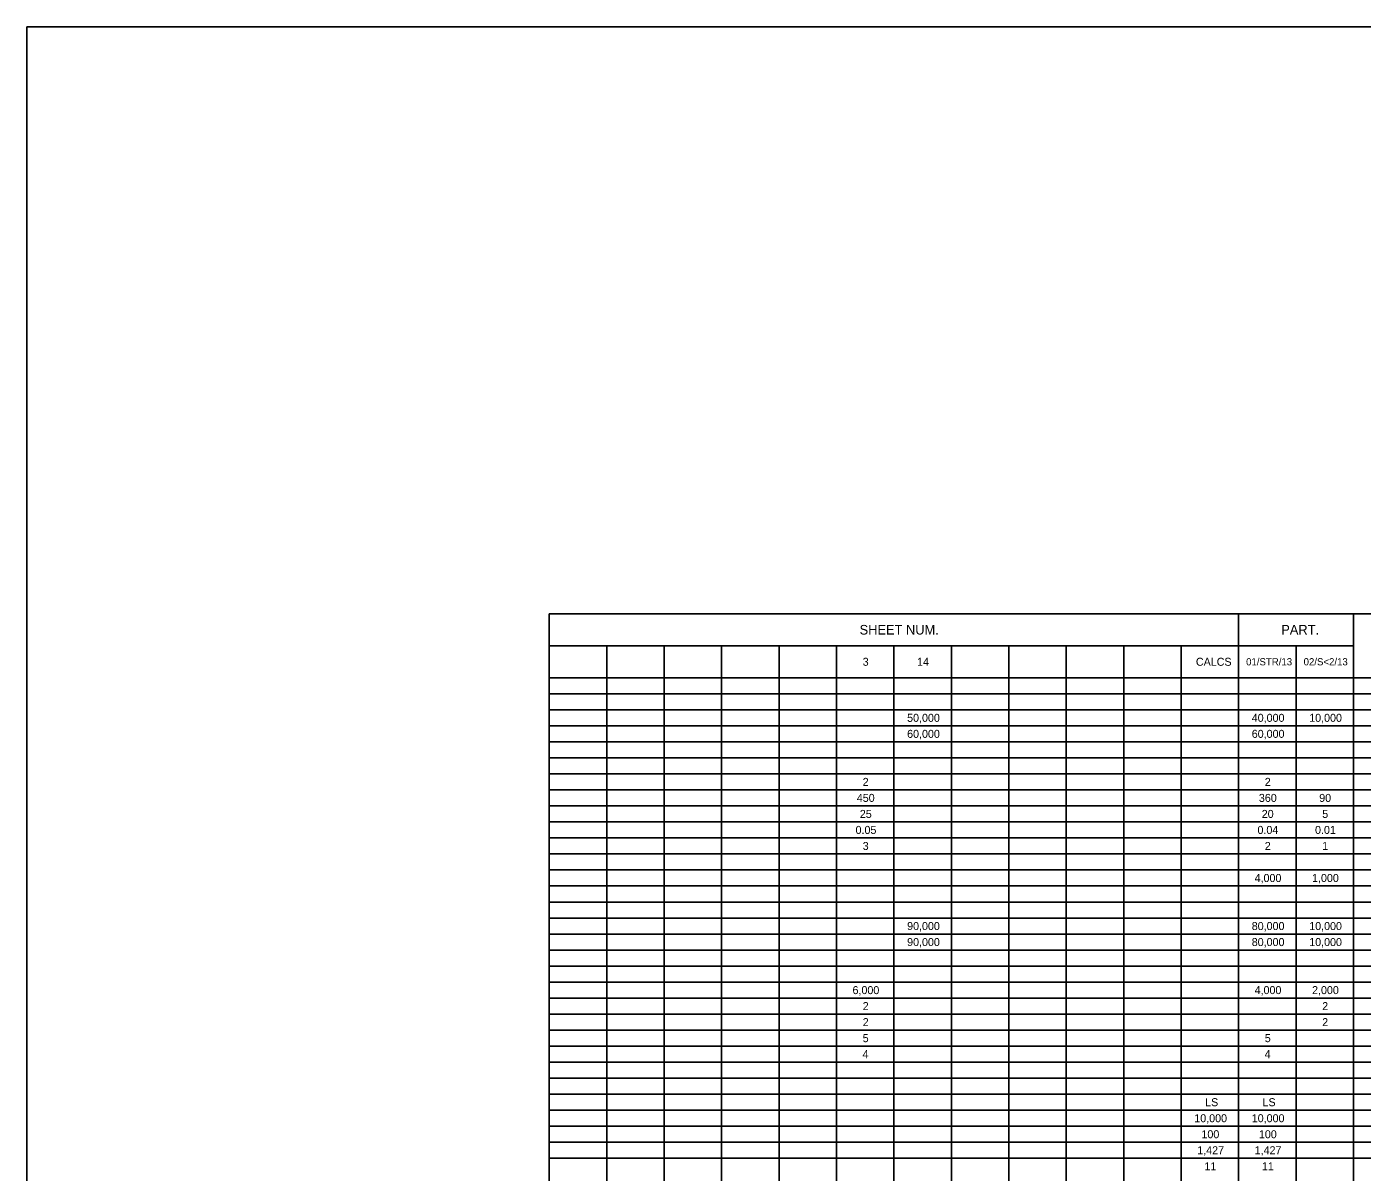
# Model space of a CAD drawing. Extents: x -58.2 to 35.9, y -5.7 to 34.4.
# Drawn here: x -58.21 to -34.85, y 14.42 to 34.45 of the extents above; entities that cross this region are included whole.
import ezdxf

# ---------------------------------------------------------------- set-up
doc = ezdxf.new("R2010")
doc.units = 0
for name, color, linetype in [('SC_Scratch1', 7, 'Continuous'), ('SH_Data', 7, 'Continuous'), ('SH_Text', 7, 'Continuous')]:
    doc.layers.add(name, color=color, linetype=linetype)

msp = doc.modelspace()

# ---------------------------------------------------------------- linework, layer by layer
at = {"layer": 'SC_Scratch1'}
msp.add_lwpolyline([(-58.206, 34.449), (-10.544, 34.449), (-10.544, -5.726), (-58.206, -5.726)], close=True, dxfattribs=at)
at = {"layer": 'SH_Data'}
for p, q in [((-49.066, 24.187), (-18.563, 24.187)), ((-49.066, 24.187), (-49.066, 3.187)), ((-37.01, 24.187), (-37.01, 3.187)), ((-35, 24.187), (-35, 3.187)), ((-49.066, 23.627), (-35, 23.627)), ((-48.061, 23.627), (-48.061, 3.187)), ((-47.057, 23.627), (-47.057, 3.187)), ((-46.052, 23.627), (-46.052, 3.187)), ((-45.047, 23.627), (-45.047, 3.187)), ((-44.043, 23.627), (-44.043, 3.187)), ((-43.038, 23.627), (-43.038, 3.187)), ((-42.033, 23.627), (-42.033, 3.187)), ((-41.028, 23.627), (-41.028, 3.187)), ((-40.024, 23.627), (-40.024, 3.187)), ((-39.019, 23.627), (-39.019, 3.187)), ((-38.014, 23.627), (-38.014, 3.187)), ((-36.005, 23.627), (-36.005, 3.187)), ((-49.066, 23.067), (-18.563, 23.067)), ((-49.066, 22.787), (-18.563, 22.787)), ((-49.066, 22.507), (-18.563, 22.507)), ((-49.066, 22.227), (-18.563, 22.227)), ((-49.066, 21.947), (-18.563, 21.947)), ((-49.066, 21.667), (-18.563, 21.667)), ((-49.066, 21.387), (-18.563, 21.387)), ((-49.066, 21.107), (-18.563, 21.107)), ((-49.066, 20.827), (-18.563, 20.827)), ((-49.066, 20.547), (-18.563, 20.547)), ((-49.066, 20.267), (-18.563, 20.267)), ((-49.066, 19.987), (-18.563, 19.987)), ((-49.066, 19.707), (-18.563, 19.707)), ((-49.066, 19.427), (-18.563, 19.427)), ((-49.066, 19.147), (-18.563, 19.147)), ((-49.066, 18.867), (-18.563, 18.867)), ((-49.066, 18.587), (-18.563, 18.587)), ((-49.066, 18.307), (-18.563, 18.307)), ((-49.066, 18.027), (-18.563, 18.027)), ((-49.066, 17.747), (-18.563, 17.747)), ((-49.066, 17.467), (-18.563, 17.467)), ((-49.066, 17.187), (-18.563, 17.187)), ((-49.066, 16.907), (-18.563, 16.907)), ((-49.066, 16.627), (-18.563, 16.627)), ((-49.066, 16.347), (-18.563, 16.347)), ((-49.066, 16.067), (-18.563, 16.067)), ((-49.066, 15.787), (-18.563, 15.787)), ((-49.066, 15.507), (-18.563, 15.507)), ((-49.066, 15.227), (-18.563, 15.227)), ((-49.066, 14.947), (-18.563, 14.947)), ((-49.066, 14.667), (-18.563, 14.667))]:
    msp.add_line(p, q, dxfattribs=at)

# ---------------------------------------------------------------- texts
at = {"layer": 'SH_Text'}
for s, height, p in [('SHEET NUM.', 0.168, (-43.638, 23.823)), ('PART.', 0.168, (-36.263, 23.823)), ('3', 0.14, (-43.584, 23.277)), ('14', 0.14, (-42.633, 23.277)), ('CALCS', 0.14, (-37.756, 23.277)), ('01/STR/13', 0.126, (-36.878, 23.284)), ('02/S<2/13', 0.126, (-35.872, 23.284)), ('50,000', 0.14, (-42.807, 22.297)), ('40,000', 0.14, (-36.779, 22.297)), ('10,000', 0.14, (-35.774, 22.297)), ('60,000', 0.14, (-42.807, 22.017)), ('60,000', 0.14, (-36.779, 22.017)), ('2', 0.14, (-43.584, 21.177)), ('2', 0.14, (-36.551, 21.177)), ('450', 0.14, (-43.687, 20.897)), ('360', 0.14, (-36.654, 20.897)), ('90', 0.14, (-35.599, 20.897)), ('25', 0.14, (-43.634, 20.617)), ('20', 0.14, (-36.604, 20.617)), ('5', 0.14, (-35.546, 20.617)), ('0.05', 0.14, (-43.709, 20.337)), ('0.04', 0.14, (-36.679, 20.337)), ('0.01', 0.14, (-35.672, 20.337)), ('3', 0.14, (-43.584, 20.057)), ('2', 0.14, (-36.551, 20.057)), ('1', 0.14, (-35.547, 20.057)), ('4,000', 0.14, (-36.729, 19.497)), ('1,000', 0.14, (-35.724, 19.497)), ('90,000', 0.14, (-42.807, 18.657)), ('80,000', 0.14, (-36.779, 18.657)), ('10,000', 0.14, (-35.774, 18.657)), ('90,000', 0.14, (-42.807, 18.377)), ('80,000', 0.14, (-36.779, 18.377)), ('10,000', 0.14, (-35.774, 18.377)), ('6,000', 0.14, (-43.762, 17.537)), ('4,000', 0.14, (-36.729, 17.537)), ('2,000', 0.14, (-35.724, 17.537)), ('2', 0.14, (-43.584, 17.257)), ('2', 0.14, (-35.547, 17.257)), ('2', 0.14, (-43.584, 16.977)), ('2', 0.14, (-35.547, 16.977)), ('5', 0.14, (-43.584, 16.697)), ('5', 0.14, (-36.551, 16.697)), ('4', 0.14, (-43.587, 16.417)), ('4', 0.14, (-36.554, 16.417)), ('LS', 0.14, (-37.594, 15.577)), ('LS', 0.14, (-36.59, 15.577)), ('10,000', 0.14, (-37.784, 15.297)), ('10,000', 0.14, (-36.779, 15.297)), ('100', 0.14, (-37.659, 15.017)), ('100', 0.14, (-36.654, 15.017)), ('1,427', 0.14, (-37.732, 14.737)), ('1,427', 0.14, (-36.728, 14.737)), ('11', 0.14, (-37.607, 14.457)), ('11', 0.14, (-36.602, 14.457))]:
    msp.add_text(s, height=height, dxfattribs=at).set_placement(p)

doc.saveas('drawing.dxf')
